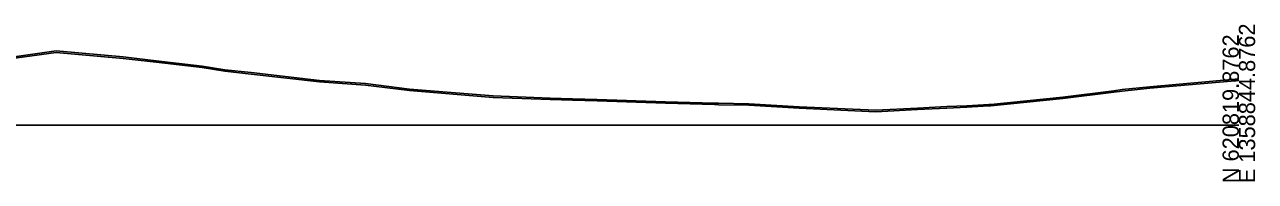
# Model space of a CAD drawing. Extents: x -26 to 803, y -27 to 3586.
# Drawn here: x 591.4 to 802.8, y 490.3 to 517.3 of the extents above; entities that cross this region are included whole.
import ezdxf

# ---------------------------------------------------------------- set-up
doc = ezdxf.new("R2010")
doc.units = 0
for name, color, linetype in [('DESIGN - SHEET - Light Grid', 7, 'Continuous'), ('SURVEY - GROUND - Bottom of Topsoil Layer', 7, 'Continuous'), ('SURVEY - GROUND - Top of Ground', 7, 'Continuous')]:
    doc.layers.add(name, color=color, linetype=linetype)

msp = doc.modelspace()

# ---------------------------------------------------------------- linework, layer by layer
at = {"layer": 'DESIGN - SHEET - Light Grid'}
msp.add_line((400, 500), (800, 500), dxfattribs=at)
at = {"layer": 'SURVEY - GROUND - Bottom of Topsoil Layer'}
for p, q in [((587.12, 511.15), (596.8, 512.52)), ((596.8, 512.52), (608.29, 511.47)), ((608.29, 511.47), (613.98, 510.81)), ((613.98, 510.81), (621.89, 509.89)), ((621.89, 509.89), (625.78, 509.27)), ((625.78, 509.27), (630.26, 508.79)), ((630.26, 508.79), (642.03, 507.44)), ((784.68, 506.34), (800, 507.7)), ((642.03, 507.44), (649.92, 506.89)), ((649.92, 506.89), (657.49, 505.96)), ((657.49, 505.96), (671.89, 504.76)), ((769.73, 504.57), (778.52, 505.65)), ((778.52, 505.65), (779.95, 505.86)), ((779.95, 505.86), (784.68, 506.34)), ((671.89, 504.76), (681.66, 504.38)), ((681.66, 504.38), (685.49, 504.27)), ((685.49, 504.27), (689.75, 504.15)), ((689.75, 504.15), (701.45, 503.76)), ((701.45, 503.76), (709.9, 503.53)), ((709.9, 503.53), (710.59, 503.51)), ((710.59, 503.51), (715.82, 503.41)), ((715.82, 503.41), (724.45, 502.89)), ((757.4, 503.32), (769.73, 504.57)), ((724.45, 502.89), (737.6, 502.29)), ((737.6, 502.29), (744.79, 502.69)), ((744.79, 502.69), (749.84, 502.93)), ((749.84, 502.93), (753.28, 503.07)), ((753.28, 503.07), (757.05, 503.3)), ((757.05, 503.3), (757.4, 503.32))]:
    msp.add_line(p, q, dxfattribs=at)
at = {"layer": 'SURVEY - GROUND - Top of Ground'}
msp.add_lwpolyline([(587.12, 511.4), (596.8, 512.77), (608.29, 511.72), (613.98, 511.06), (621.89, 510.14), (625.78, 509.52), (630.26, 509.04), (642.03, 507.69), (649.92, 507.14), (657.49, 506.21), (671.89, 505.01), (681.66, 504.63), (685.49, 504.52), (689.75, 504.4), (701.45, 504.01), (709.9, 503.78), (710.59, 503.76), (715.82, 503.66), (724.45, 503.14), (737.6, 502.54), (744.79, 502.94), (749.84, 503.18), (753.28, 503.32), (757.05, 503.55), (757.4, 503.57), (769.73, 504.82), (778.52, 505.9), (779.95, 506.11), (784.68, 506.59), (800, 507.95)], dxfattribs=at)

# ---------------------------------------------------------------- texts
at = {"layer": 'DESIGN - SHEET - Light Grid'}
for s, p in [('E 1358844.8762', (802.8, 490)), ('N 620819.8762', (800, 490))]:
    msp.add_text(s, height=2.8, rotation=90, dxfattribs=at).set_placement(p)

doc.saveas('drawing.dxf')
